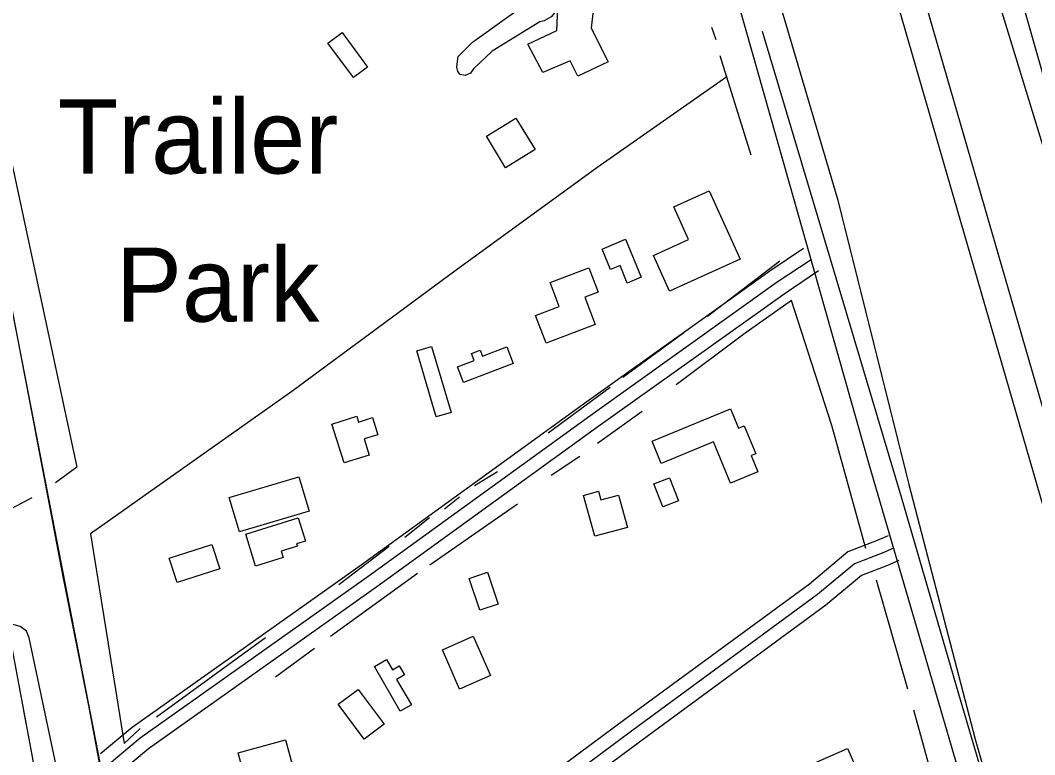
# Model space of a CAD drawing. Extents: x 3281947 to 3319794, y 715894 to 741249.
# Drawn here: x 3291541 to 3292679, y 731891 to 732714 of the extents above; entities that cross this region are included whole.
import ezdxf

# ---------------------------------------------------------------- set-up
doc = ezdxf.new("R2010")
doc.units = 0
for name, color, linetype in [('V-BLDG-IDEN', 7, 'Continuous'), ('V-BLDG-OTLN', 7, 'Continuous'), ('V-BORW-LINE', 7, 'Continuous'), ('V-LEVE-TOET', 7, 'Continuous'), ('V-RAIL-TRAK', 7, 'Continuous'), ('V-ROAD-CNTR', 7, 'Continuous'), ('V-SITE-VEGE', 7, 'Continuous'), ('V-SURV-LINE', 7, 'Continuous'), ('V-TOPO-SHOR', 7, 'Continuous'), ('V-UTIL-LINE', 7, 'Continuous'), ('V-WETL-SWMP', 7, 'Continuous')]:
    doc.layers.add(name, color=color, linetype=linetype)

msp = doc.modelspace()

# ---------------------------------------------------------------- linework, layer by layer
at = {"layer": 'V-BLDG-OTLN'}
for points in [[(3292142.5, 732702.7), (3292143.7, 732727.6), (3292183.2, 732724.9), (3292181.2, 732705.2), (3292200.2, 732667.4), (3292166.1, 732651.6), (3292157.7, 732668.7), (3292127.1, 732655.4), (3292110.3, 732687.3)], [(3291930.5, 732661.6), (3291914.6, 732649.9), (3291886, 732688.4), (3291901.9, 732700.2)], [(3292118.4, 732569.1), (3292085.2, 732548.8), (3292063.6, 732584.1), (3292096.8, 732604.4)], [(3292348.2, 732446.3), (3292269, 732410.5), (3292250.9, 732450.6), (3292290.4, 732468.4), (3292273.9, 732505.1), (3292313.6, 732523)], [(3292237.3, 732426.1), (3292221.6, 732419.6), (3292213.5, 732439.1), (3292202.8, 732434.7), (3292193.3, 732457.7), (3292219.6, 732468.7)], [(3292130.5, 732352), (3292118.7, 732383.1), (3292145.4, 732393.2), (3292135.2, 732420.1), (3292178.7, 732436.6), (3292189, 732409.4), (3292174, 732403.7), (3292185.7, 732372.9)], [(3292024, 732274.5), (3292007.4, 732269.6), (3291985.6, 732343.4), (3292002.2, 732348.3)], [(3292086.5, 732348), (3292093.6, 732329.5), (3292038, 732308.1), (3292031.3, 732325.5), (3292050.1, 732332.8), (3292047.1, 732340.6), (3292056.6, 732344.3), (3292059.2, 732337.5)], [(3291932.1, 732226.7), (3291904, 732218), (3291890.4, 732261.5), (3291918.3, 732270.2), (3291920.3, 732263.8), (3291936, 732268.8), (3291942, 732249.6), (3291926.5, 732244.8)], [(3292249.5, 732242.4), (3292337.5, 732278.6), (3292346.4, 732257), (3292352.8, 732259.6), (3292365.7, 732228.3), (3292360.6, 732226.2), (3292368.1, 732208), (3292337.4, 732195.4), (3292318.5, 732241.4), (3292259.8, 732217.3)], [(3291864.8, 732164), (3291786.8, 732140.7), (3291775.4, 732179), (3291853.4, 732202.2)], [(3292279.1, 732175.5), (3292261.5, 732168.6), (3292251.4, 732194.5), (3292268.9, 732201.4)], [(3292221.7, 732145.7), (3292185.3, 732135.7), (3292172.7, 732181.5), (3292189.5, 732186.1), (3292192.1, 732176.5), (3292211.7, 732181.9)], [(3291793.9, 732137.9), (3291852.7, 732156.2), (3291860.8, 732130.2), (3291850.9, 732127.2), (3291851.8, 732124.5), (3291833.6, 732118.9), (3291835.8, 732111.9), (3291804.9, 732102.3)], [(3291764.7, 732099.3), (3291716.9, 732083.9), (3291708.1, 732111.1), (3291755.9, 732126.6)], [(3292076.9, 732059.7), (3292056.4, 732052.8), (3292044.3, 732088.5), (3292064.8, 732095.4)], [(3292068.4, 731979.5), (3292033.6, 731964.2), (3292014.3, 732008.3), (3292049, 732023.6)], [(3291979.5, 731946.8), (3291967.1, 731939.6), (3291938, 731989.7), (3291951.6, 731997.6), (3291958.3, 731986.2), (3291965.9, 731990.6), (3291971.8, 731980.4), (3291963, 731975.3)], [(3291926.7, 731908.4), (3291897.6, 731947.4), (3291919.9, 731964), (3291949, 731925)], [(3291857.2, 731838.5), (3291828.4, 731830.5), (3291819.6, 731862.4), (3291795.5, 731855.8), (3291785.3, 731893), (3291838.2, 731907.6)], [(3292484.4, 731862.2), (3292441, 731842.9), (3292439.3, 731846.8), (3292428.7, 731842.1), (3292417.1, 731868.2), (3292427.9, 731873), (3292425.4, 731878.8), (3292468.5, 731898)]]:
    msp.add_lwpolyline(points, close=True, dxfattribs=at)
at = {"layer": 'V-BORW-LINE'}
msp.add_spline([(3293535.9, 730584.4), (3293535.4, 730585.3), (3293497, 730657.8), (3293473.2, 730709), (3293458.5, 730751), (3293474.3, 730774.9), (3293498.1, 730803.8), (3293503.4, 730822.7), (3293477.8, 730865.6), (3293442, 730902.7), (3293433.9, 730945), (3293411.4, 730975.9), (3293373.6, 730999.6), (3293329.4, 731009.5), (3293303.1, 731048.1), (3293262.2, 731107.9), (3293205.3, 731214.8), (3293152.6, 731305), (3293107.1, 731394.1), (3293067.5, 731500.7), (3293026.1, 731639), (3292993.6, 731735.4), (3292952.7, 731872.8), (3292925.4, 731981.1), (3292877.6, 732144.9), (3292823.1, 732324.3), (3292751.1, 732547.8), (3292686.3, 732753.5), (3292626.9, 732959.9), (3292578, 733149.6), (3292517.3, 733327.2), (3292468.2, 733513.4), (3292419.2, 733671.8), (3292416, 733774.3), (3292443.1, 733955.9), (3292470.5, 734116.1), (3292505.3, 734342.4), (3292539, 734502.7), (3292585.4, 734750.4), (3292605.6, 734909.3), (3292653.5, 735109.1), (3292667, 735197.9), (3292695.9, 735272.4), (3292816.4, 735423.9), (3292992.8, 735589.4), (3293118.5, 735717.8), (3293151.4, 735720.6), (3293212.8, 735688.5), (3293267.6, 735628.9), (3293299.6, 735578.7), (3293301.8, 735551.8), (3293258, 735404.8), (3293178.9, 735247.8), (3293118.6, 735154.6), (3293020.3, 735075.8), (3292963, 735023.3), (3292899.5, 734947.4), (3292877.5, 734825.5), (3292893.6, 734715.3), (3292909.1, 734596.9), (3292894.2, 734486.7), (3292877, 734359.2), (3292869.2, 734210.8), (3292882, 734024.1), (3292899.4, 733885.4), (3292922.7, 733752.5), (3292923.7, 733661.1), (3292932, 733561), (3292981.6, 733412.2), (3293062.5, 733212.5), (3293111.5, 733047.6), (3293198.7, 732785.6), (3293276, 732606.5), (3293315.6, 732497), (3293336.7, 732448.1), (3293389.1, 732447.8), (3293396.1, 732434.3), (3293380.9, 732420.2), (3293299, 732384.1), (3293266.7, 732364.9), (3293242, 732348.4), (3293249.1, 732332.4), (3293352.9, 732375.1), (3293457.9, 732401.3), (3293485.1, 732328.5), (3293556.5, 732096.9), (3293588.1, 731935.2), (3293608.4, 731793.7), (3293628.6, 731696.8), (3293641.6, 731601.6), (3293698.6, 731490.3), (3293768.8, 731439), (3293849.4, 731356), (3293937.4, 731250.3), (3293976, 731184.6), (3294065.4, 731012.3)], degree=3, dxfattribs=at)
at = {"layer": 'V-LEVE-TOET'}
for points in [[(3292116.6, 733726.4), (3292119.1, 733710.8), (3292160.5, 733534.6), (3292278.1, 733161.5), (3292360.2, 732842.1), (3292398.4, 732713.4), (3292457.8, 732512.4), (3292537.4, 732193.7), (3292611.6, 731908.2), (3292708.8, 731568.3), (3292740.3, 731460.7), (3292780.4, 731364), (3292812.9, 731289.4), (3292841.9, 731225.5), (3292874.9, 731155.3), (3293007.9, 730907.9)], [(3293316.8, 730986.4), (3293308.8, 730990.5), (3293298, 730998.4), (3293288.3, 731007.5), (3293278.7, 731018.4), (3293240, 731069.5), (3293160.6, 731223.3), (3293060, 731402.8), (3293030.2, 731458.1), (3293021.3, 731475.1), (3293015.1, 731491.8), (3293009.2, 731507.7), (3293002.8, 731527.2), (3292933.1, 731757), (3292849.6, 732017.2), (3292830.2, 732083.1), (3292830.2, 732090.8), (3292830.6, 732094.2), (3292830.8, 732102.3), (3292828.9, 732112.4), (3292728.7, 732439.8), (3292603.7, 732848.8)]]:
    msp.add_lwpolyline(points, dxfattribs=at)
at = {"layer": 'V-RAIL-TRAK'}
msp.add_lwpolyline([(3291932.2, 730932.3), (3291902.5, 730997.1), (3291863.3, 731084), (3291851.6, 731113), (3291818.8, 731193.6), (3291794.2, 731259.5), (3291772.9, 731318.7), (3291753.8, 731375.9), (3291728.7, 731455.9), (3291715.5, 731504.8), (3291696.3, 731576.5), (3291674.8, 731664.2), (3291651, 731776.6), (3291631.9, 731869.8), (3291617.7, 731945.9), (3291589, 732090.6), (3291555.4, 732267.7), (3291504.8, 732529.4), (3291469.4, 732713.8), (3291434.9, 732893), (3291409.9, 733023.3), (3291378.4, 733188.8), (3291346.7, 733355.5), (3291314, 733529.1)], dxfattribs=at)
at = {"layer": 'V-ROAD-CNTR'}
for points in [[(3291933.6, 730934.6), (3291880.7, 731046.9), (3291824, 731191.5), (3291779, 731306.6), (3291728.4, 731459.3), (3291692.2, 731598.3), (3291652, 731772.4), (3291593.7, 732071.8), (3291531.9, 732390.4), (3291492.6, 732605.5), (3291447.5, 732834.4), (3291394, 733112.5), (3291336.5, 733407.1), (3291274.4, 733732.2), (3291200.7, 734125.4), (3291141, 734429.6), (3291086.7, 734716.9), (3291050.9, 734904.4), (3290972, 735312.2), (3290886.8, 735758.9), (3290812, 736149.3)], [(3292971.1, 730923), (3292872, 731117), (3292817.2, 731219.5), (3292783.6, 731284), (3292753.8, 731349.2), (3292730.2, 731404.5), (3292711.3, 731460.3), (3292655.9, 731658.9), (3292493.2, 732214.9), (3292347.1, 732730.2), (3292123.3, 733487.2), (3292095.5, 733596.9), (3292079.2, 733679.3), (3292077.9, 733740.5)], [(3292419.4, 732458.2), (3292381.4, 732432.7), (3292171, 732282.7), (3291923.4, 732103.4), (3291666.3, 731921.3), (3291631.1, 731891.7)], [(3292427.7, 732445.7), (3292389.9, 732420.4), (3292179.7, 732270.5), (3291932.2, 732091.2), (3291675.5, 731909.4), (3291640.7, 731880.2)], [(3292436.1, 732433.3), (3292398.5, 732408), (3292188.5, 732258.3), (3291940.9, 732079), (3291684.7, 731897.5), (3291650.4, 731868.7)], [(3292514.2, 732136.2), (3292501.9, 732130.8), (3292468.9, 732118.1), (3292425.9, 732082.2), (3292218.9, 731930.4), (3292024.2, 731785.6), (3291888.3, 731689.1), (3291833.1, 731644.8)], [(3292520.2, 732122.4), (3292507.6, 732116.9), (3292476.6, 732105), (3292435.1, 732070.4), (3292227.8, 731918.3), (3292033, 731773.5), (3291897.4, 731677.2), (3291842.5, 731633.1)], [(3292526.2, 732108.7), (3292513.3, 732103), (3292484.4, 732091.9), (3292444.4, 732058.5), (3292236.8, 731906.2), (3292041.8, 731761.4), (3291906.4, 731665.2), (3291851.9, 731621.4)]]:
    msp.add_lwpolyline(points, dxfattribs=at)
at = {"layer": 'V-SITE-VEGE'}
msp.add_lwpolyline([(3292032.1, 732673.3), (3292048.2, 732689.7), (3292127.1, 732746.5), (3292132.5, 732748.5), (3292137.9, 732748.4), (3292143, 732747.7), (3292145.3, 732744.9), (3292145.6, 732741.2), (3292144.6, 732737.6), (3292142.5, 732733.9), (3292141.8, 732726.8), (3292140.4, 732722.7), (3292136.2, 732718), (3292128.4, 732713.4), (3292123.4, 732712.2), (3292070.1, 732679.3), (3292049.3, 732659.7), (3292045.7, 732654.9), (3292040, 732652.2), (3292034.3, 732653.4), (3292031.6, 732656.7), (3292030.4, 732661.1), (3292030.7, 732665.1)], close=True, dxfattribs=at)
at = {"layer": 'V-SURV-LINE'}
for points in [[(3292270.7, 733717.1), (3292717.5, 732175.8)], [(3292688.7, 732167.4), (3292241.9, 733708.8)]]:
    msp.add_lwpolyline(points, dxfattribs=at)
at = {"layer": 'V-TOPO-SHOR'}
for p, q in [((3292321.3, 732692.1), (3292316.6, 732705.8)), ((3292360.5, 732562.8), (3292325.7, 732674.2)), ((3292311.5, 732382.6), (3292392.7, 732444.5)), ((3292216.6, 732314), (3292285.1, 732364.1)), ((3292202.3, 732302.6), (3292133, 732251.3)), ((3292238.5, 732275.5), (3292188.4, 732239.8)), ((3292168.4, 732225.3), (3292136.4, 732203.8)), ((3292050.4, 732192.7), (3292076.2, 732208.2)), ((3292016.8, 732166.4), (3292033.5, 732180.1)), ((3292098.5, 732171.8), (3292000.2, 732103.2)), ((3291972.1, 732134.7), (3291999.9, 732156.6)), ((3291898.1, 732081.8), (3291954.8, 732124.5)), ((3291986.3, 732094), (3291889, 732023.2)), ((3292536.2, 731964.2), (3292501.2, 732086.6)), ((3291693.7, 731933.4), (3291815.8, 732022.4)), ((3291870.9, 732009.9), (3291827.2, 731977.9)), ((3292569.3, 731846.2), (3292543.1, 731940.9)), ((3291657.6, 731903.5), (3291675.6, 731920.4))]:
    msp.add_line(p, q, dxfattribs=at)
for points in [[(3292372.8, 732701.7), (3292435.4, 732492.9), (3292528.9, 732179.8), (3292593, 731959), (3292673.3, 731686.3), (3292734.1, 731473), (3292744.8, 731436.7), (3292754.6, 731411.7), (3292769.7, 731380.2), (3292784.9, 731347.4), (3292797.9, 731318.2), (3292814.6, 731276), (3292919.1, 731070.5), (3293087.5, 730750.2), (3293239, 730461.6), (3293375.2, 730193.6), (3293501, 729954.3), (3293601.8, 729775), (3293681.5, 729668.1), (3293803.3, 729528.3)], [(3292333.1, 732650.6), (3292187.6, 732548.8), (3292029.9, 732434.1), (3291845.4, 732297.9), (3291619.8, 732138.3), (3291657.6, 731903.5)], [(3291514.5, 732632.4), (3291604.5, 732213.1), (3291580.5, 732195.7)], [(3292489.3, 732122.2), (3292451.2, 732259.7), (3292405.7, 732400), (3292352.3, 732362.3), (3292276.4, 732305.3)], [(3291553.9, 732178.8), (3291412.2, 732103.7), (3291352.1, 732067.5), (3291337.8, 732057.3), (3291326.3, 732048.3), (3291309.3, 732025.5), (3291294.1, 732003.9), (3291204, 731905.2)], [(3291584.1, 731864.7), (3291551, 732022), (3291547.8, 732029.3), (3291540.8, 732034.7), (3291534, 732036.6), (3291527.1, 732037.2), (3291515.2, 732033.8), (3291504.7, 732029.3), (3291312.5, 731889.9), (3291085.9, 731725), (3290684.6, 731430.3), (3290251.4, 731117.8), (3290137.1, 731028.7)]]:
    msp.add_lwpolyline(points, dxfattribs=at)
at = {"layer": 'V-UTIL-LINE'}
for points in [[(3290106.1, 739458.5), (3290330.7, 738283.9), (3290559.1, 737084), (3290785.9, 735894.2), (3290899.5, 735297.4), (3291017.3, 734692.5), (3291128.9, 734105.7), (3291356.8, 732913.2), (3291474.1, 732317.9), (3291585.8, 731719.9), (3291701.1, 731121.7), (3291817.6, 730525.1), (3291929.6, 729931.5)], [(3291544.7, 731940.2), (3291550.9, 731906.7)]]:
    msp.add_lwpolyline(points, dxfattribs=at)
at = {"layer": 'V-WETL-SWMP'}
msp.add_lwpolyline([(3293242.1, 736812), (3293232.1, 735969.6), (3293242.1, 735829.2), (3293272.1, 735779.1), (3293346.9, 735732.1), (3293357.8, 735673.5), (3293299.3, 735657.1), (3293212, 735769), (3293184.2, 735772.3), (3293151.3, 735776), (3293101.8, 735759), (3293021.6, 735688.8), (3292891.3, 735548.4), (3292761.1, 735398), (3292660.9, 735297.7), (3292620.8, 735237.5), (3292370.3, 733773.3), (3292400.3, 733663), (3292811.2, 732218.9), (3292828.6, 732036.6), (3293081.7, 731326.4), (3293270.4, 730981.3)], dxfattribs=at)

# ---------------------------------------------------------------- texts
at = {"layer": 'V-BLDG-IDEN'}
for s, p in [('Trailer', (3291583, 732542.3)), ('Park', (3291648.2, 732376.3))]:
    msp.add_text(s, height=83, dxfattribs=at).set_placement(p)

doc.saveas('drawing.dxf')
